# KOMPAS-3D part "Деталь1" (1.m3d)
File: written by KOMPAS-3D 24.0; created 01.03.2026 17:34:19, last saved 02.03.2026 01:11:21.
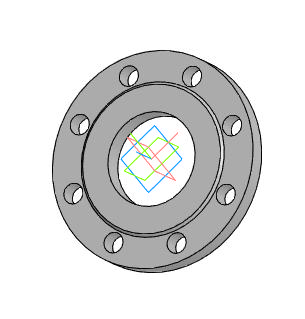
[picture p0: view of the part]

Document properties: Автор: R2D2; Полное имя файла: E:\Работа\Зайцев\GVWR3131M-2W-F-S Задвижка клиновая с выдвижным штоком DN.ru Ду50-100 Ру40\исходные материалы\DN100\1.m3d

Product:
- Part/product: Деталь1
    Масса: 5.351688
    additional columns: Типовые

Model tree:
1. Эскиз:2
2. Элемент вращения:1
     Угол 1 = 360
3. Эскиз:3  (with: Грань.Элемент вращения:1)
4. Элемент выдавливания:2
     Расстояние 2 = 21
5. Массив по концентрической сетке:1  (with: Элемент выдавливания:2, Эскиз:3, Грань.Элемент вращения:1)  (8 pattern instances)
     Шаг 2 = 360
6. Эскиз:4  (with: Грань.Элемент вращения:1)
7. Элемент выдавливания:3
     Расстояние 2 = 3

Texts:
  Линейный размер с обрывом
